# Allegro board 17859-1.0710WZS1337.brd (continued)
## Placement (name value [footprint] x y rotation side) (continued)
PC4702  SC10U25V3MX-GP  [C603H40]  54.22 58.35 90 top
PC4703  SC10U25V3MX-GP  [C603H40]  54.22 56.52 90 top
PC4704  SC10U25V3MX-GP  [C603H40]  54.22 56.52 270 bottom
PC4706  SC1KP50V2KX-1DLGP  [C402H22]  64.56 62.69 90 top
PC4707  SCD22U25V3KX-DL-GP  [C603H36]  48.39 60.96 90 top
PC4708  SC1U10V2KX-1DLGP  [C402H22]  51.33 63.85 270 bottom
PC4766  SC1U10V2KX-1DLGP  [C402H22]  53.79 64.34 180 bottom
PC4802  SC10U25V3MX-GP  [C603H40]  52.55 68.68 90 top
PC4803  SC10U25V3MX-GP  [C603H40]  52.55 68.68 270 bottom
PC4804  SC10U25V3MX-GP  [C603H40]  52.55 66.86 270 bottom
PC4805  SC10U25V3MX-GP  [C603H40]  52.55 66.86 90 top
PC4808  SCD22U25V3KX-DL-GP  [C603H36]  47.77 71.81 90 top
PC4809  SC1U10V2KX-1DLGP  [C402H22]  50.84 74.15 270 bottom
PC4810  SC1KP50V2KX-1DLGP  [C402H22]  55.99 77.54 90 bottom
PC4811  SCD22U25V3KX-DL-GP  [C603H36]  49.5 81.99 90 top
PC4812  SC1U10V2KX-1DLGP  [C402H22]  51.84 88.22 90 top
PC4813  SC1KP50V2KX-1DLGP  [C402H22]  63.88 86.13 270 bottom
PC4814  SC10U25V3MX-GP  [C603H40]  53.84 76.51 270 bottom
PC4815  SC10U25V3MX-GP  [C603H40]  53.84 78.31 270 bottom
PC4816  SC10U25V3MX-GP  [C603H40]  53.84 76.51 90 top
PC4817  SC10U25V3MX-GP  [C603H40]  53.84 78.31 90 top
PC4866  SC1U10V2KX-1DLGP  [C402H22]  53.13 87.76 180 top
PC4877  SC1U10V2KX-1DLGP  [C402H22]  52.78 74.73 180 bottom
PC5001  SC2D2U10V3KX-1DLGP-U  [C603H36]  90.16 105.95 270 top
PC5002  SC10U25V5KX-DL-GP  [C805H58]  89.66 99.94 0 bottom
PC5003  SC10U25V5KX-DL-GP  [C805H58]  90.49 96.89 180 bottom
PC5004  SCD1U25V2KX-1-DL-GP  [C402H22]  90.95 100.42 0 bottom
PC5005  SCD22U25V3KX-DL-GP  [C603H36]  87.9 102.57 90 top
PC5104  SC22U6D3V3MX-L1-GP  [C603H40]  41.83 11.67 0 top
PC5105  SC22U6D3V3MX-L1-GP  [C603H40]  40.56 11.67 0 top
PC5107  SC22U6D3V3MX-L1-GP  [C603H40]  41.7 16.5 180 top
PC5108  SC1U10V2KX-L1-GP  [C402H22]  55.57 10.34 0 bottom
PC5109  SC22U6D3V3MX-L1-GP  [C603H40]  40.43 16.5 180 top
PC5111  SC10U25V3MX-GP  [C603H40]  47.82 16.56 180 top
PC5112  SC4D7U6D3V3KX-L-GP  [C603H36]  57.17 10.85 90 bottom
PC5113  SCD1U25V2KX-L-GP  [C402H22]  56.79 14.53 270 bottom
PC5114  SCD1U25V2KX-L-GP  [C402H22]  49.93 17.43 0 bottom
PC5115  SC10U25V3MX-GP  [C603H40]  48.69 16.77 0 bottom
PC5116  SCD1U25V2KX-L-GP  [C402H22]  50.64 16.13 180 top
PC5117  SC10U6D3V3MX-L-GP  [C603H38]  55.59 16.44 0 bottom
PC5118  SC1500P50V2KX-2GP  [C402H22]  44.34 11.08 270 top
PC5122  SC1U10V2KX-L1-GP  [C402H22]  51.78 16.41 270 top
PC5124  SC10U6D3V3MX-L-GP  [C603H38]  54.1 16.64 0 bottom
PC5125  SC10U6D3V3MX-DL-GP  [C603H36]  74.19 15.37 0 bottom
PC5126  SC68P50V2JN-1DLGP  [C402H22]  63.85 14.3 180 bottom
PC5127  SC22U6D3V5MX-2DLGP  [C805H54]  61.36 12.93 180 bottom
PC5128  SC10U6D3V3MX-DL-GP  [C603H36]  62.2 16.28 0 bottom
PC5129  SCD1U25V2KX-1-DL-GP  [C402H22]  71.67 12.75 0 bottom
PC5130  SC1U10V2KX-1DLGP  [C402H22]  71.95 15.78 0 bottom
PC5201  SC22U6D3V3MX-1-DL-GP  [C603H40]  148.25 56.54 270 top
PC5202  SC1U10V2KX-1GP  [C402H22]  146.37 69.94 90 bottom
PC5203  SC22U6D3V3MX-1-DL-GP  [C603H40]  148.28 57.84 270 top
PC5204  SCD1U25V2KX-GP  [C402H22]  146.65 67.72 180 bottom
PC5205  SC22U6D3V3MX-1-DL-GP  [C603H40]  154.02 56.92 270 bottom
PC5206  SC22U6D3V3MX-1-DL-GP  [C603H40]  148.25 56.54 90 bottom
PC5208  SCD1U25V2KX-GP  [C402H22]  148.38 60.15 270 top
PC5209  SC10U25V5KX-DL-GP  [C805H58]  154.76 65.36 180 bottom
PC5210  SC10U25V5KX-DL-GP  [C805H58]  155.95 69.8 270 bottom
PC5211  SC10U25V5KX-GP  [C805H56]  156.38 68 270 bottom
PC5212  SC220P50V2KX-3GP  [C402H22]  153.44 73.69 90 bottom
PC5213  SCD01U25V2KX-3DLGP  [C402H22]  146.86 70.82 90 bottom
PC5214  SCD1U25V2KX-1-DL-GP  [C402H22]  157.37 67.69 90 top
PC5215  SC1KP50V2KX-1DLGP  [C402H22]  149.88 73.64 0 bottom
PC5216  SC10U25V5KX-GP  [C805H56]  156.56 65.61 180 bottom
PC5301  SC68P50V2JN-1DLGP  [C402H22]  85.52 14.28 180 bottom
PC5302  SC22U6D3V5MX-2DLGP  [C805H54]  82.75 14.38 90 bottom
PC5303  SC10U6D3V3MX-DL-GP  [C603H36]  82.87 15.93 90 bottom
PC5304  SC4700P50V2KX-1DLGP  [C402H22]  91.82 12.45 270 top
PC5305  SC1U10V2KX-1DLGP  [C402H22]  91.98 14.64 0 top
PC5306  SC10U6D3V3MX-DL-GP  [C603H36]  92.45 17.55 270 bottom
PC8501  SCD1U25V2KX-1-DL-GP  [C402H22]  125.37 95.07 0 bottom
PC8502  SC10U25V3MX-GP  [C603H40]  127.15 105.41 180 bottom
PC8503  SC10U25V3MX-GP  [C603H40]  126.44 95 180 top
PC8504  SC10U25V3MX-GP  [C603H40]  127.71 95 180 top
PC8505  SC10U25V3MX-GP  [C603H40]  127.71 95 0 bottom
PC8506  SC1U10V2KX-1DLGP  [C402H22]  123.87 100.08 90 top
PC8507  SCD1U25V2KX-1-DL-GP  [C402H22]  115.23 102.24 270 top
PC8508  SC330P50V2JN-1-DL-GP  [C402H22]  136.65 106.5 270 top
PC8509  SCD1U25V2KX-1-DL-GP  [C402H22]  122.4 104.12 0 top
PC8510  SC1KP50V2KX-1DLGP  [C402H22]  115.77 103.58 180 bottom
PC8511  SC10U25V3MX-GP  [C603H40]  127.15 105.41 0 top
PC8512  SC10U25V3MX-GP  [C603H40]  125.85 105.41 180 bottom
PC8513  SC10U25V3MX-GP  [C603H40]  126.44 95 0 bottom
PC8514  SCD1U16V2KX-3DLGP  [C402H22]  115.49 98.38 270 top
PC8515  SC10U25V3MX-GP  [C603H40]  125.85 105.41 0 top
PC8516  SCD1U25V2KX-1-DL-GP  [C402H22]  124.81 105.21 0 top
PC8517  SCD1U25V2KX-1-DL-GP  [C402H22]  122.52 96.98 180 top
PC8518  SC33P50V2JN-3DLGP  [C402H22]  117.55 100.84 90 bottom
PC8519  SC2700P50V2KX-1-DL-GP  [C402H22]  115.46 97.61 90 top
PC8520  SC330P50V2JN-1-DL-GP  [C402H22]  137.13 94.9 0 top
PC8521  SCD01U25V2KX-3DLGP  [C402H22]  115.64 96.85 90 top
PC8522  SCD1U25V2KX-1-DL-GP  [C402H22]  117.42 104.07 90 top
PC8523  SC47P50V2JN-5DLGP  [C402H22]  118.33 96.04 0 top
PC8524  SC47P50V2JN-5DLGP  [C402H22]  117.49 98.86 180 top
PC8525  SC47P50V2JN-5DLGP  [C402H22]  117.52 95.91 0 top
PC8526  SCD1U25V2KX-1-DL-GP  [C402H22]  119.04 104.04 270 top
PC8602  SC330P50V2KX-3GP  [C402H22]  183.86 57.08 0 top
PC8609  SCD01U25V2KX-3DLGP  [C402H22]  183.56 49.86 0 top
PC8610  SC10U25V3MX-GP  [C603H40]  181.81 49.84 0 top
PC8611  SC22U6D3V3MX-1-DL-GP  [C603H40]  187.73 57.53 180 top
PC8613  SC22U6D3V3MX-1-DL-GP  [C603H40]  190.39 50.9 0 top
PC8614  SCD1U16V2KX-3GP  [C402H22]  188.59 50.88 0 top
PC8615  SC10U25V3MX-GP  [C603H40]  181.65 49.84 180 bottom
PC8616  SCD1U16V2KX-3GP  [C402H22]  180.82 57.2 180 top
PC8617  SC2D2U10V3KX-1GP  [C603H36]  186.43 57.2 180 top
PC8618  SC1U10V2KX-1GP  [C402H22]  185.41 57.31 180 top
PC8619  SCD1U25V2KX-GP  [C402H22]  184.27 50.12 0 bottom
PC8620  SC22U6D3V3MX-1-DL-GP  [C603H40]  189.02 57.53 180 top
PC8621  SC22U6D3V3MX-1-DL-GP  [C603H40]  187.34 50.88 0 top
PC8627  SC10U6D3V3MX-GP  [C603H38]  144.65 87.12 0 bottom
PC8628  SC22U6D3V3MX-1-DL-GP  [C603H40]  152.24 84.53 180 bottom
PC8629  SC1U10V2KX-1GP  [C402H22]  143.38 82.98 90 bottom
PC8630  SC10U6D3V3MX-GP  [C603H38]  143.38 86.85 0 bottom
PC8631  SC22U6D3V3MX-1-DL-GP  [C603H40]  153.51 84.53 180 bottom
PC8632  SC22P50V2JN-4GP  [C402H22]  148.46 82.83 0 bottom
PD4401  BAT54C-12-GP  [SOT-23-9H44]  102.28 16.26 270 bottom
PD4404  L1SS355T1G-GP  [SOD323AKH44]  173.68 17.27 270 bottom
PD4407  RB520S30-GP  [SOD523AKH26]  167.43 4.22 270 top
PD4408  BAT54C-12-GP  [SOT-23-9H44]  106.22 16.23 270 bottom
PD4409  RB751V-40H-GP  [SOD323AKH38]  138.4 16.08 90 top
PD4411  RB520S30-GP  [SOD523AKH26]  139.06 18.62 270 top
PD5101  AZ4024-01L-R7G-GP  [SOD323AKH40]  49.32 17.02 0 top
PDA1  GNDPADSR375-GP  [GNDPADSR351-131-S-NP]  175.51 104.98 0 top
PDA2  GNDPADSR375-GP  [GNDPADSR351-131-S-NP]  175.51 104.98 180 bottom
PG4401  GAP-CLOSE-PWR-3-GP  [GAP-CLOSE-PWR-3]  152.09 12.88 0 bottom
PG4402  GAP-CLOSE-PWR-3-GP  [GAP-CLOSE-PWR-3]  152.09 11.84 0 bottom
PG4405  GAP-CLOSE-PWR-3-GP  [GAP-CLOSE-PWR-3]  133.7 7.7 0 top
PG4406  GAP-CLOSE-PWR-3-GP  [GAP-CLOSE-PWR-3]  133.62 5.87 0 top
PG4408  GAP-CLOSE-PWR-3-GP  [GAP-CLOSE-PWR-3]  159.15 7.32 0 bottom
PG4501  GAP-CLOSE-PWR-3-GP  [GAP-CLOSE-PWR-3]  57.86 7.44 180 bottom
PG4502  GAP-CLOSE-PWR-3-GP  [GAP-CLOSE-PWR-3]  57.85 7.42 180 top
PG4503  GAP-CLOSE-PWR-3-GP  [GAP-CLOSE-PWR-3]  57.85 8.18 180 top
PG4504  GAP-CLOSE-PWR-3-GP  [GAP-CLOSE-PWR-3]  57.86 8.21 180 bottom
PG4505  GAP-CLOSE-PWR-3-GP  [GAP-CLOSE-PWR-3]  57.85 8.95 180 top
PG4506  GAP-CLOSE-PWR-3-GP  [GAP-CLOSE-PWR-3]  57.86 8.97 180 bottom
PG4507  GAP-CLOSE-PWR-3-GP  [GAP-CLOSE-PWR-3]  38.82 7.6 180 bottom
PG4508  GAP-CLOSE-PWR-3-GP  [GAP-CLOSE-PWR-3]  38.82 8.36 180 bottom
PG4509  GAP-CLOSE-PWR-3-GP  [GAP-CLOSE-PWR-3]  38.82 5.31 180 bottom
PG4510  GAP-CLOSE-PWR-3-GP  [GAP-CLOSE-PWR-3]  38.82 6.07 180 bottom
PG4511  GAP-CLOSE-PWR-3-GP  [GAP-CLOSE-PWR-3]  38.82 4.55 180 bottom
PG4512  GAP-CLOSE-PWR-3-GP  [GAP-CLOSE-PWR-3]  38.82 6.84 180 bottom
PG4513  GAP-CLOSE-PWR-3-GP  [GAP-CLOSE-PWR-3]  38.82 3.03 180 bottom
PG4514  GAP-CLOSE-PWR-3-GP  [GAP-CLOSE-PWR-3]  38.82 3.79 180 bottom
PG4515  GAP-CLOSE-PWR-3-GP  [GAP-CLOSE-PWR-3]  198.02 42.58 90 top
PG4516  GAP-CLOSE-PWR-3-GP  [GAP-CLOSE-PWR-3]  199.55 42.58 90 top
PG4517  GAP-CLOSE-PWR-3-GP  [GAP-CLOSE-PWR-3]  198.79 42.58 90 top
PG4518  GAP-CLOSE-PWR-3-GP  [GAP-CLOSE-PWR-3]  197.26 42.58 90 top
PG4519  GAP-CLOSE-PWR-3-GP  [GAP-CLOSE-PWR-3]  183.87 47.07 180 top
PG4520  GAP-CLOSE-PWR-3-GP  [GAP-CLOSE-PWR-3]  183.87 47.83 180 top
PG4521  GAP-CLOSE-PWR-3-GP  [GAP-CLOSE-PWR-3]  183.87 45.54 180 top
PG4522  GAP-CLOSE-PWR-3-GP  [GAP-CLOSE-PWR-3]  183.87 44.02 180 top
PG4523  GAP-CLOSE-PWR-3-GP  [GAP-CLOSE-PWR-3]  183.87 46.31 180 top
PG4524  GAP-CLOSE-PWR-3-GP  [GAP-CLOSE-PWR-3]  183.87 44.78 180 top
PG4527  GAP-CLOSE-PWR-3-GP  [GAP-CLOSE-PWR-3]  39.29 3.38 0 top
PG4528  GAP-CLOSE-PWR-3-GP  [GAP-CLOSE-PWR-3]  53.13 4.27 0 top
PG4529  GAP-CLOSE-PWR-3-GP  [GAP-CLOSE-PWR-3]  58.19 2.9 180 top
PG4530  GAP-CLOSE-PWR-3-GP  [GAP-CLOSE-PWR-3]  185.21 48.14 270 top
PG4531  GAP-CLOSE-PWR-3-GP  [GAP-CLOSE-PWR-3]  200.2 49.1 180 top
PG4532  GAP-CLOSE-PWR-3-GP  [GAP-CLOSE-PWR-3]  194.02 51.21 90 top
PG4533  GAP-CLOSE-PWR-3-GP  [GAP-CLOSE-PWR-3]  56.64 9.91 270 top
PG4534  GAP-CLOSE-PWR-3-GP  [GAP-CLOSE-PWR-3]  55.87 9.91 270 top
PG4707  GAP-CLOSE-PWR-3-GP  [GAP-CLOSE-PWR-3]  60.37 62.82 180 bottom
PG4708  GAP-CLOSE-PWR-3-GP  [GAP-CLOSE-PWR-3]  62.53 62.82 0 bottom
PG4709  GAP-CLOSE-PWR-3-GP  [GAP-CLOSE-PWR-3]  43.58 108.59 90 top
PG4710  GAP-CLOSE-PWR-3-GP  [GAP-CLOSE-PWR-3]  42.82 108.59 90 top
PG4711  GAP-CLOSE-PWR-3-GP  [GAP-CLOSE-PWR-3]  42.06 108.59 90 top
PG4712  GAP-CLOSE-PWR-3-GP  [GAP-CLOSE-PWR-3]  41.29 108.59 90 top
PG4713  GAP-CLOSE-PWR-3-GP  [GAP-CLOSE-PWR-3]  40.53 108.59 90 top
PG4714  GAP-CLOSE-PWR-3-GP  [GAP-CLOSE-PWR-3]  50.39 62.99 0 bottom
PG4715  GAP-CLOSE-PWR-3-GP  [GAP-CLOSE-PWR-3]  50.39 62.23 0 bottom
PG4716  GAP-CLOSE-PWR-3-GP  [GAP-CLOSE-PWR-3]  50.39 61.47 0 bottom
PG4717  GAP-CLOSE-PWR-3-GP  [GAP-CLOSE-PWR-3]  50.39 60.71 0 bottom
PG4718  GAP-CLOSE-PWR-3-GP  [GAP-CLOSE-PWR-3]  50.39 59.95 0 bottom
PG4808  GAP-CLOSE-PWR-3-GP  [GAP-CLOSE-PWR-3]  60.41 72.64 180 bottom
PG4809  GAP-CLOSE-PWR-3-GP  [GAP-CLOSE-PWR-3]  62.7 72.64 0 bottom
PG4813  GAP-CLOSE-PWR-3-GP  [GAP-CLOSE-PWR-3]  60.35 81.83 180 bottom
PG4815  GAP-CLOSE-PWR-3-GP  [GAP-CLOSE-PWR-3]  62.63 81.85 0 bottom
PG4816  GAP-CLOSE-PWR-3-GP  [GAP-CLOSE-PWR-3]  49.55 76.74 0 top
PG4817  GAP-CLOSE-PWR-3-GP  [GAP-CLOSE-PWR-3]  49.55 77.5 0 top
PG4818  GAP-CLOSE-PWR-3-GP  [GAP-CLOSE-PWR-3]  49.55 78.26 0 top
PG4819  GAP-CLOSE-PWR-3-GP  [GAP-CLOSE-PWR-3]  49.55 79.02 0 top
PG4820  GAP-CLOSE-PWR-3-GP  [GAP-CLOSE-PWR-3]  49.55 79.78 0 top
PG4821  GAP-CLOSE-PWR-3-GP  [GAP-CLOSE-PWR-3]  49.47 78.97 0 bottom
PG4822  GAP-CLOSE-PWR-3-GP  [GAP-CLOSE-PWR-3]  49.47 78.21 0 bottom
PG4823  GAP-CLOSE-PWR-3-GP  [GAP-CLOSE-PWR-3]  49.47 77.45 0 bottom
PG4824  GAP-CLOSE-PWR-3-GP  [GAP-CLOSE-PWR-3]  49.04 76.23 270 bottom
PG4825  GAP-CLOSE-PWR-3-GP  [GAP-CLOSE-PWR-3]  48.28 76.23 270 bottom
PG5001  GAP-CLOSE-PWR-3-GP  [GAP-CLOSE-PWR-3]  100.76 100.43 0 bottom
PG5002  GAP-CLOSE-PWR-3-GP  [GAP-CLOSE-PWR-3]  86.92 97.85 180 bottom
PG5003  GAP-CLOSE-PWR-3-GP  [GAP-CLOSE-PWR-3]  86.92 98.61 180 bottom
PG5011  GAP-CLOSE-PWR-3-GP  [GAP-CLOSE-PWR-3]  98.55 100.43 180 bottom
PG5101  GAP-CLOSE-PWR-3-GP  [GAP-CLOSE-PWR-3]  50.59 13.13 180 top
PG5102  GAP-CLOSE-PWR-3-GP  [GAP-CLOSE-PWR-3]  50.59 13.9 180 top
PG5103  GAP-CLOSE-PWR-3-GP  [GAP-CLOSE-PWR-3]  50.59 14.84 180 top
PG5106  GAP-CLOSE-PWR-3-GP  [GAP-CLOSE-PWR-3]  38.65 15.48 180 bottom
PG5107  GAP-CLOSE-PWR-3-GP  [GAP-CLOSE-PWR-3]  38.65 12.43 180 bottom
PG5108  GAP-CLOSE-PWR-3-GP  [GAP-CLOSE-PWR-3]  38.65 13.2 180 bottom
PG5109  GAP-CLOSE-PWR-3-GP  [GAP-CLOSE-PWR-3]  38.65 13.96 180 bottom
PG5110  GAP-CLOSE-PWR-3-GP  [GAP-CLOSE-PWR-3]  52.09 17.5 270 top
PG5111  GAP-CLOSE-PWR-3-GP  [GAP-CLOSE-PWR-3]  38.65 16.24 180 bottom
PG5113  GAP-CLOSE-PWR-3-GP  [GAP-CLOSE-PWR-3]  39.41 11.76 90 top
PG5115  GAP-CLOSE-PWR-3-GP  [GAP-CLOSE-PWR-3]  38.65 14.72 180 bottom
PG5116  GAP-CLOSE-PWR-3-GP  [GAP-CLOSE-PWR-3]  53.03 17.5 270 top
PG5120  GAP-CLOSE-PWR-3-GP  [GAP-CLOSE-PWR-3]  57.17 16.67 180 bottom
PG5121  GAP-CLOSE-PWR-3-GP  [GAP-CLOSE-PWR-3]  57.17 15.75 180 bottom
PG5122  GAP-CLOSE-PWR-3-GP  [GAP-CLOSE-PWR-3]  60.27 15.52 90 bottom
PG5123  GAP-CLOSE-PWR-3-GP  [GAP-CLOSE-PWR-3]  61.03 15.52 90 bottom
PG5201  GAP-CLOSE-PWR-3-GP  [GAP-CLOSE-PWR-3]  152.23 55.58 270 bottom
PG5204  GAP-CLOSE-PWR-3-GP  [GAP-CLOSE-PWR-3]  152.99 55.81 270 top
PG5206  GAP-CLOSE-PWR-3-GP  [GAP-CLOSE-PWR-3]  150.71 55.58 270 bottom
PG5207  GAP-CLOSE-PWR-3-GP  [GAP-CLOSE-PWR-3]  152.99 55.58 270 bottom
PG5208  GAP-CLOSE-PWR-3-GP  [GAP-CLOSE-PWR-3]  152.23 55.81 270 top
PG5209  GAP-CLOSE-PWR-3-GP  [GAP-CLOSE-PWR-3]  150.71 55.81 270 top
PG5210  GAP-CLOSE-PWR-3-GP  [GAP-CLOSE-PWR-3]  157.82 69.71 180 top
PG5211  GAP-CLOSE-PWR-3-GP  [GAP-CLOSE-PWR-3]  151.47 55.81 270 top
PG5212  GAP-CLOSE-PWR-3-GP  [GAP-CLOSE-PWR-3]  157.82 68.95 180 top
PG5213  GAP-CLOSE-PWR-3-GP  [GAP-CLOSE-PWR-3]  149.95 55.81 270 top
PG5214  GAP-CLOSE-PWR-3-GP  [GAP-CLOSE-PWR-3]  157.82 70.47 180 top
PG5215  GAP-CLOSE-PWR-3-GP  [GAP-CLOSE-PWR-3]  149.95 55.58 270 bottom
PG5216  GAP-CLOSE-PWR-3-GP  [GAP-CLOSE-PWR-3]  151.47 55.58 270 bottom
PG5223  GAP-CLOSE-PWR-6-GP  [GAP-CLOSE-PWR]  154.22 55.83 180 bottom
PG5301  GAP-CLOSE-PWR-3-GP  [GAP-CLOSE-PWR-3]  83.28 15.88 90 top
PG5302  GAP-CLOSE-PWR-3-GP  [GAP-CLOSE-PWR-3]  81.76 15.88 90 top
PG5303  GAP-CLOSE-PWR-3-GP  [GAP-CLOSE-PWR-3]  82.52 15.88 90 top
PG8605  GAP-CLOSE-PWR-3-GP  [GAP-CLOSE-PWR-3]  144.8 81.74 90 bottom
PG8606  GAP-CLOSE-PWR-3-GP  [GAP-CLOSE-PWR-3]  144.04 81.74 90 bottom
PG8607  GAP-CLOSE-PWR-3-GP  [GAP-CLOSE-PWR-3]  154.91 85.58 0 bottom
PG8608  GAP-CLOSE-PWR-3-GP  [GAP-CLOSE-PWR-3]  154.91 84.81 0 bottom
PG8609  GAP-CLOSE-PWR-3-GP  [GAP-CLOSE-PWR-3]  190.7 52.17 0 bottom
PG8610  GAP-CLOSE-PWR-3-GP  [GAP-CLOSE-PWR-3]  190.7 53.7 0 bottom
PG8611  GAP-CLOSE-PWR-3-GP  [GAP-CLOSE-PWR-3]  190.7 52.94 0 bottom
PG8612  GAP-CLOSE-PWR-3-GP  [GAP-CLOSE-PWR-3]  190.7 51.41 0 bottom
PG8613  GAP-CLOSE-PWR-3-GP  [GAP-CLOSE-PWR-3]  190.11 57.1 90 top
PG8614  GAP-CLOSE-PWR-3-GP  [GAP-CLOSE-PWR-3]  178.18 53.11 0 top
PG8615  GAP-CLOSE-PWR-3-GP  [GAP-CLOSE-PWR-3]  178.18 52.35 0 top
PG8616  GAP-CLOSE-PWR-3-GP  [GAP-CLOSE-PWR-3]  178.18 51.59 0 top
PG8617  GAP-CLOSE-PWR-3-GP  [GAP-CLOSE-PWR-3]  178.18 50.83 0 top
PG8618  GAP-CLOSE-PWR-3-GP  [GAP-CLOSE-PWR-3]  190.7 56.75 0 bottom
PG8619  GAP-CLOSE-PWR-3-GP  [GAP-CLOSE-PWR-3]  190.7 54.46 0 bottom
PG8620  GAP-CLOSE-PWR-3-GP  [GAP-CLOSE-PWR-3]  190.7 55.22 0 bottom
PG8621  GAP-CLOSE-PWR-3-GP  [GAP-CLOSE-PWR-3]  190.7 55.98 0 bottom
PL4401  IND-4D7UH-291-GP  [L11102530H158]  142.92 11.36 90 bottom
PL4501  COIL-1D5UH-43-GP  [L4947-1015H119]  189.43 46.41 90 bottom
PL4502  IND-1D5UH-23-GP-U  [L7066-1830-UH119]  44.75 5.54 270 bottom
PL4701  COIL-D15UH-2-GP  [L7366-1930H158]  61.47 62.82 270 bottom
PL4801  COIL-D15UH-2-GP  [L7366-1930H158]  61.55 72.64 270 bottom
PL4802  COIL-D15UH-2-GP  [L7366-1930H158]  61.5 81.95 270 bottom
PL5001  IND-D47UH-22-GP-U  [L7066-1830-UH119]  99.67 100.7 270 bottom
PL5101  COIL-1UH-34-GP-U1  [L7066-1830-UH119]  43.63 13.59 90 bottom
PL5201  COIL-1UH-34-GP-U1  [L7066-1830-UH119]  150.13 61.67 180 bottom
PL8508  IND-D15UH-33-GP  [L7366-1830H119]  139.54 103.91 270 bottom
PL8509  IND-D15UH-33-GP  [L7366-1830H119]  139.54 96.8 270 bottom
PL8602  IND-1UH-300-GP  [L2520-D620H48]  149.96 86.52 270 bottom
PL8603  COIL-1UH-73-GP  [L4947-1115H119]  186.91 53.55 270 bottom
PQ4402  2N7002K-2-GP  [SOT23DGS2D4H44]  214.17 58.37 0 top
PQ4405  2N7002KDW-1-GP  [SOT-363H44]  169.21 12.91 180 bottom
PQ4408  MMBT3906-3-GP  [SOT23CBE2D4H44]  166.54 15.95 270 bottom
PQ4415  2N7002KDW-1-GP  [SOT-363H44]  165.09 7.34 270 bottom
PQ4416  2N7002KDW-1-GP  [SOT-363H44]  166.31 10.62 180 bottom
PQ4417  2N7002K-2-GP  [SOT23DGS2D4H44]  96.95 5.87 0 top
PQ4418  2N7002KDW-1-GP  [SOT-363H44]  99.89 9.43 0 top
PR4401  D01R6F-1-GP  [R1206H38]  150.16 12.45 180 bottom
PR4402  2D2R3-1-U-GP  [R603H22]  165.88 13.46 270 top
PR4403  2D2R5J-1-GP  [R805H24]  164.33 4.93 90 top
PR4404  150KR2F-L-GP  [R402H16]  156.97 4.63 180 top
PR4405  4D7R2F-GP  [R402H16]  161.87 5.44 270 top
PR4406  18K7R2F-GP  [R402H16]  158.52 4.68 0 top
PR4407  D01R3721F-GP-U  [R3720H40]  131.46 6.71 0 top
PR4409  100KR2F-L1-GP  [R402H16]  157.02 6.91 180 bottom
PR4410  105KR2F-1-GP  [R402H16]  155.77 7.57 270 bottom
PR4411  100R2F-L1-GP-U  [R402H14]  155.87 9.2 90 bottom
PR4412  -  [0R0402-PAD]  155.75 10.75 270 bottom
PR4413  12K1R2F-L1-GP  [R402H16]  155.75 11.51 90 bottom
PR4414  -  [0R0805-PAD]  165.91 13.03 270 bottom
PR4416  2D2R3J-2-GP  [R603H22]  142.41 5.46 270 top
PR4417  100KR2F-L1-GP  [R402H16]  161.59 6.91 0 bottom
PR4420  0R3J-0-U-GP  [R603H22]  160.95 15.83 180 top
PR4422  1R2F-GP  [R402H16]  168.14 8.23 270 top
PR4423  2D2R2F-GP  [R402H16]  168.55 8.99 270 top
PR4424  2D2R2F-GP  [R402H16]  157.75 17.83 0 top
PR4425  0R2F-1-GP  [R402H16]  156.97 17.83 0 top
PR4426  196KR2F-GP  [R402H16]  172.23 6.28 90 top
PR4427  100KR2F-L2-GP  [R402H16]  169.49 4.98 0 top
PR4429  100KR2F-L2-GP  [R402H16]  159.1 6.45 90 bottom
PR4430  100KR2J-1-GP  [R402H16]  97.35 7.83 270 top
PR4431  -  [0R0402-PAD]  99.05 6.76 0 top
PR4432  0R2J-L-GP  [R402H15]  99.82 6.12 0 top
PR4433  -  [0R0402-PAD]  99.71 4.9 270 top
PR4434  0R2F-1-GP  [R402H16]  167.38 6.28 90 top
PR4435  100KR2F-L3-GP  [R402H16]  168.98 9.83 90 bottom
PR4436  1MR2J-1-GP  [R402H16]  167.25 16.82 180 top
PR4437  0R2F-1-GP  [R402H16]  168.14 5.51 90 top
PR4438  0R2J-2-GP  [R402H16]  160.98 16.16 180 bottom
PR4439  1KR2F-3-GP  [R402H16]  153.11 8.26 270 bottom
PR4440  D001R2512F-8-GP  [R2512-4H35]  133.19 9.22 90 bottom
PR4441  0R3J-0-U-GP  [R603H22]  141.45 12.37 90 top
PR4443  0R3J-0-U-GP  [R603H22]  154.71 16.46 270 bottom
PR4444  0R0603-PAD-1-GP-U  [0R0603-PAD-U]  162.58 15.65 90 bottom
PR4445  0R2F-1-GP  [R402H16]  162.78 14 270 top
PR4446  0R3J-0-U-GP  [R603H22]  162.22 15.57 0 top
PR4447  127KR2F-GP  [R402H16]  154.71 7.22 270 top
PR4448  200KR2F-L-GP  [R402H16]  154.71 6.45 90 top
PR4449  200KR2F-L-GP  [R402H16]  170.25 4.98 0 top
PR4450  10KR2F-2-GP  [R402H16]  170.53 13.54 90 top
PR4451  95K3R2F-GP  [R402H16]  160.83 6.91 180 bottom
PR4453  0R2J-2-GP  [R402H16]  159.94 16.44 0 top
PR4462  -  [0R0402-PAD]  164.64 16.72 0 top
PR4463  0R2J-2-GP  [R402H16]  171.34 8.36 0 top
PR4464  10KR2F-2-GP  [R402H16]  97.45 9.63 0 top
PR4465  100KR2F-L1-GP  [R402H16]  99.08 11.74 0 top
PR4466  0R2J-2-GP  [R402H16]  118.41 14.18 90 top
PR4472  100KR2F-L3-GP  [R402H16]  170.25 10.29 0 bottom
PR4473  100KR2J-1-GP  [R402H16]  168.52 16.84 0 top
PR4474  100KR2F-L1-GP  [R402H16]  168.22 15.32 90 top
PR4475  680KR2F-GP  [R402H16]  165.4 16.72 180 top
PR4476  -  [0R0402-PAD]  169.51 9.96 90 top
PR4477  0R0402-PAD-1-GP  [0R0402-PAD]  171.75 14.35 0 top
PR4478  100R2F-L1-GP-U  [R402H14]  154.91 13.95 90 bottom
PR4479  D001R2512F-8-GP  [R2512-4H35]  151.38 11.36 180 top
PR4480  0R2F-1-GP  [R402H16]  159 15.57 0 bottom
PR4483  D01R3721F-GP-U  [R3720H40]  122.3 4.93 180 top
PR4484  0R2F-1-GP  [R402H16]  159.79 5.44 90 top
PR4485  182KR2F-GP  [R402H16]  159.79 6.23 270 top
PR4486  0R0402-PAD-1-GP  [0R0402-PAD]  157.93 15.83 180 top
PR4487  0R0402-PAD-1-GP  [0R0402-PAD]  156.18 16.51 90 top
PR4488  0R0402-PAD-1-GP  [0R0402-PAD]  165.93 7.75 270 top
PR4489  0R0402-PAD-1-GP  [0R0402-PAD]  167.61 11.1 270 top
PR4490  0R2F-1-GP  [R402H16]  165.53 11.99 0 top
PR4491  7K15R2F-L-GP  [R402H16]  166.29 11.99 180 top
PR4492  NTC-220K-5-GP-U  [NTC-402H24-U]  168.65 13.29 180 top
PR4493  0R2F-1-GP  [R402H16]  156.13 8.84 180 top
PR4494  470KR2J-L1-GP  [R402H15]  135.58 17.3 270 top
PR4495  0R2J-2-GP  [R402H16]  138.78 17.35 270 top
PR4496  D01R3721F-GP-U  [R3720H40]  126.69 11.61 0 top
PR4501  -  [0R0603-PAD]  191.92 43.46 0 top
PR4502  -  [0R0603-PAD]  49.91 6.71 270 top
PR4503  10KR2F-2-GP  [R402H16]  194.53 52.38 90 top
PR4504  0R0402-PAD-1-GP  [0R0402-PAD]  54.27 2.49 0 bottom
PR4505  100KR2J-1-GP  [R402H16]  200.2 49.99 270 top
PR4506  1KR2F-3-GP  [R402H16]  194.91 51.13 180 top
PR4507  1KR2F-3-GP  [R402H16]  52.75 2.24 0 bottom
PR4508  200KR2F-L1-GP  [R402H16]  199.46 51.69 270 top
PR4509  1KR2F-3-GP  [R402H16]  200.04 50.9 270 top
PR4510  100KR2J-1-GP  [R402H16]  57.07 3.3 180 top
PR4511  1KR2F-3-GP  [R402H16]  57.14 2.18 0 bottom
PR4512  200KR2F-L1-GP  [R402H16]  55.8 2.49 180 bottom
PR4513  1MR2J-1-GP  [R402H16]  55.04 2.49 180 bottom
PR4514  1MR2J-1-GP  [R402H16]  197.12 52.43 90 top
PR4515  0R0402-PAD-1-GP  [0R0402-PAD]  195.78 52.83 0 top
PR4516  0R0402-PAD-1-GP  [0R0402-PAD]  197.12 53.22 270 top
PR4530  10KR2F-2-GP  [R402H16]  194.53 53.27 90 top
PR4551  348KR2F-GP  [R402H16]  53.51 2.24 0 top
PR4601  0R0402-PAD-1-GP  [0R0402-PAD]  48.94 66.68 270 bottom
PR4602  0R0402-PAD-1-GP  [0R0402-PAD]  48.61 65.92 270 bottom
PR4603  1KR2F-3-GP  [R402H16]  38.68 62.03 0 top
PR4604  100R2F-L3-GP  [R402H16]  40.96 62.03 0 top
PR4605  75R2F-2-GP  [R402H16]  40.2 62.03 0 top
PR4606  45D3R2F-L-GP  [R402H16]  39.44 62.03 0 top
PR4607  100R2F-L3-GP  [R402H16]  37.64 61.29 0 bottom
PR4608  76K8R2F-GP  [R402H16]  36.21 62.72 90 top
PR4609  10KR2F-L1-GP  [R402H15]  36.86 61.49 0 bottom
PR4610  1R2J-GP  [R402H16]  41.17 60.15 0 bottom
PR4611  NTC-10K-26-GP-U  [NTC-402H22-U]  97.15 105.9 90 bottom
PR4612  0R0402-PAD-1-GP  [0R0402-PAD]  43.73 60.89 0 bottom
PR4613  0R0402-PAD-1-GP  [0R0402-PAD]  46.53 63.97 270 bottom
PR4614  0R2J-L-GP  [R402H15]  38.42 64.26 180 top
PR4615  1KR2F-3-GP  [R402H16]  46.3 63.07 90 bottom
PR4616  8K06R2F-GP  [R402H16]  35.12 61.85 90 bottom
PR4617  NTC-470K-8-GP-U  [NTC-402H22-U]  49.07 68.86 0 top
PR4618  11KR2F-L-GP  [R402H16]  45.1 65.18 180 bottom
PR4620  430R2F-GP  [R402H16]  44.27 64.39 180 bottom
PR4621  27K4R2F-GP  [R402H16]  33.3 60.43 0 bottom
PR4622  10R2F-L1-GP  [R402H16]  40.23 61.09 0 bottom
PR4623  0R0402-PAD-1-GP  [0R0402-PAD]  39.47 61.34 0 bottom
PR4624  49D9R2F-L1-GP  [R402H16]  38.14 59.59 90 bottom
PR4625  2K61R2F-1-GP  [R402H16]  48.96 65.13 270 bottom
PR4626  3K3R2F-2-GP  [R402H16]  35.12 62.61 270 bottom
PR4627  100R2F-L1-GP-U  [R402H14]  41.12 64.85 90 top
PR4628  9K31R2F-GP  [R402H16]  46.25 62.28 270 bottom
PR4629  100KR2F-L1-GP  [R402H16]  46.02 61.51 270 bottom
PR4630  2KR2F-L1-GP  [R402H16]  35.12 63.38 270 bottom
PR4631  100R2F-L1-GP-U  [R402H14]  31.34 64.49 90 bottom
PR4632  301R2F-GP  [R402H16]  46.25 68.07 90 bottom
PR4633  2K55R2F-GP  [R402H16]  35.12 64.14 270 bottom
PR4635  1KR2F-3-GP  [R402H16]  36.04 73.87 180 bottom
PR4636  499R2F-2-GP  [R402H16]  35.18 65.68 270 bottom
PR4637  1K78R2F-GP  [R402H16]  46.25 67.31 270 bottom
PR4638  2KR2F-L1-GP  [R402H16]  45 67.54 180 bottom
PR4639  100R2F-L1-GP-U  [R402H14]  35.43 66.93 0 bottom
PR4640  2K49R2F-2-L-GP  [R402H16]  45.03 69.27 0 bottom
PR4641  2K61R2F-1-GP  [R402H16]  32.76 68.3 0 bottom
PR4642  357R2F-GP  [R402H16]  34.8 70.06 90 bottom
PR4643  11KR2F-L-GP  [R402H16]  33.53 68.29 0 bottom
PR4644  40K2R2F-GP  [R402H16]  41.08 67 270 top
PR4645  1KR2F-L1-GP  [R402H15]  34.79 70.85 90 bottom
PR4646  NTC-10K-26-GP-U  [NTC-402H22-U]  56.92 67.92 270 bottom
PR4647  0R0402-PAD-1-GP  [0R0402-PAD]  33.09 70.36 90 bottom
PR4648  255R2F-L-GP  [R402H16]  45 70.51 270 bottom
PR4649  0R0402-PAD-1-GP  [0R0402-PAD]  45.18 73.56 180 bottom
PR4650  NTC-10K-26-GP-U  [NTC-402H22-U]  56.92 67.13 90 bottom
PR4651  1KR2F-L1-GP  [R402H15]  45 71.28 270 bottom
PR4652  11KR2F-L-GP  [R402H16]  43.96 73.15 270 bottom
PR4653  2K61R2F-1-GP  [R402H16]  44.04 75.47 270 bottom
PR4654  NTC-470K-8-GP-U  [NTC-402H22-U]  48.43 59.67 270 top
PR4655  27K4R2F-GP  [R402H16]  37.13 73.64 180 bottom
PR4656  2K87R2F-1-GP  [R402H16]  38.81 73.69 0 bottom
PR4657  2KR2F-L1-GP  [R402H16]  40.66 71.78 90 bottom
PR4658  499R2F-2-GP  [R402H16]  40.35 73.08 0 bottom
PR4659  100R2F-L1-GP-U  [R402H14]  42.36 71.78 270 bottom
PR4660  1K91R2F-1-GP  [R402H16]  41.11 73.08 0 bottom
PR4661  84K5R2F-GP  [R402H16]  37.52 74.89 270 bottom
PR4662  10KR2F-L1-GP  [R402H15]  39.01 71.35 45 bottom
PR4663  100R2F-L1-GP-U  [R402H14]  40.58 75.87 270 bottom
PR4665  0R0402-PAD-1-GP  [0R0402-PAD]  31.34 65.26 270 bottom
PR4666  0R0402-PAD-1-GP  [0R0402-PAD]  31.41 67.8 270 bottom
PR4667  0R0402-PAD-1-GP  [0R0402-PAD]  41.88 74.64 180 bottom
PR4668  0R0402-PAD-1-GP  [0R0402-PAD]  42.7 74.63 180 bottom
PR4669  0R2J-L-GP  [R402H15]  36.04 72.04 180 bottom
PR4670  267R2F-1-GP  [R402H16]  35.55 69.14 90 bottom
PR4671  1K54R2F-GP  [R402H16]  35.17 64.92 270 bottom
PR4672  100KR2F-L1-GP  [R402H16]  36.21 61.95 90 top
PR4701  0R0402-PAD-1-GP  [0R0402-PAD]  46.68 71.94 90 bottom
PR4702  0R0402-PAD-1-GP  [0R0402-PAD]  49.17 65.48 270 top
PR4703  2D2R6J-3-GP  [R1206H28]  61.26 62.69 90 top
PR4704  2D2R2F-GP  [R402H16]  51.31 64.62 270 bottom
PR4705  2D2R3F-L-GP  [R603H24]  48.38 62.23 90 top
PR4706  0R0402-PAD-1-GP  [0R0402-PAD]  49.17 64.71 270 top
PR4708  3K65R2F-1-GP  [R402H16]  44.19 76.23 90 bottom
PR4712  5K11R2F-L1-GP  [R402H16]  49.17 66.25 270 top
PR4802  0R0402-PAD-1-GP  [0R0402-PAD]  48.08 75.82 270 top
PR4803  2D2R2F-GP  [R402H16]  51.51 74.91 270 bottom
PR4804  2D2R3-1-U-GP  [R603H22]  47.24 73.08 90 top
PR4805  2D2R6J-3-GP  [R1206H28]  58.78 77.32 90 bottom
PR4806  0R0402-PAD-1-GP  [0R0402-PAD]  47.97 74.21 270 top
PR4808  3K65R2F-1-GP  [R402H16]  32.28 72.7 270 bottom
PR4809  10R2F-L1-GP  [R402H16]  33.22 71.66 270 bottom
PR4810  2D2R3-1-U-GP  [R603H22]  48.69 83.26 90 top
PR4811  0R0402-PAD-1-GP  [0R0402-PAD]  49.45 86.44 270 top
PR4812  0R0402-PAD-1-GP  [0R0402-PAD]  49.83 84.41 270 top
PR4813  2D2R2F-GP  [R402H16]  51.89 87.38 90 top
PR4814  2D2R6J-3-GP  [R1206H28]  61.13 86.57 270 bottom
PR4815  10R2F-L1-GP  [R402H16]  32.28 73.46 90 bottom
PR4816  3K65R2F-1-GP  [R402H16]  33.93 75.77 270 bottom
PR4817  5K11R2F-L1-GP  [R402H16]  48.08 75.02 270 top
PR4818  5K11R2F-L1-GP  [R402H16]  50.67 87.38 0 top
PR4821  100KR2F-L1-GP  [R402H16]  34.67 72.49 90 bottom
PR4822  100KR2F-L1-GP  [R402H16]  33.09 74.98 270 bottom
PR4823  100KR2F-L1-GP  [R402H16]  35.2 74.58 0 bottom
PR4824  100KR2F-L1-GP  [R402H16]  34.67 73.26 270 bottom
PR5001  2D2R3F-L-GP  [R603H24]  87.29 104.4 180 top
PR5003  3K65R2F-1-GP  [R402H16]  99.53 105.26 0 bottom
PR5004  0R0402-PAD-1-GP  [0R0402-PAD]  100.3 105.26 0 bottom
PR5101  10K2R2F-GP  [R402H16]  54.53 13.72 180 top
PR5102  6K49R2F-1-GP  [R402H16]  54.27 9.96 90 bottom
PR5103  510KR2F-GP  [R402H16]  57.35 12.22 90 bottom
PR5104  100KR2J-1-GP  [R402H16]  59.58 11.92 90 bottom
PR5105  0R0402-PAD-1-GP  [0R0402-PAD]  57.35 12.98 90 bottom
PR5106  0R0402-PAD-1-GP  [0R0402-PAD]  57.7 13.74 90 bottom
PR5107  6K2R2F-GP  [R402H16]  56.23 13.77 0 top
PR5108  10R2J-L-GP  [R402H16]  57.86 9.86 90 bottom
PR5109  0R0402-PAD-1-GP  [0R0402-PAD]  59.58 12.7 90 bottom
PR5110  2D2R6J-3-GP  [R1206H28]  47.19 11.08 270 top
PR5111  0R0805-PAD-1-GP-U  [0R0805-PAD-U]  51.25 16.79 0 bottom
PR5112  29K4R2F-GP  [R402H16]  62.68 14.3 180 bottom
PR5113  13K7R2F-GP  [R402H16]  63.85 12.73 180 bottom
PR5114  10KR2F-2-GP  [R402H16]  71.98 13.9 90 bottom
PR5115  47KR2J-2-GP  [R402H16]  72.46 12.68 0 bottom
PR5116  0R0402-PAD-1-GP  [0R0402-PAD]  74.26 12.68 180 bottom
PR5201  88K7R2F-GP  [R402H16]  153.64 70.77 0 bottom
PR5202  3K16R2F-GP  [R402H16]  153.41 72.93 90 bottom
PR5203  100KR2F-L1-GP  [R402H16]  150.64 73.89 0 bottom
PR5204  10KR2F-2-GP  [R402H16]  152.04 72.77 0 bottom
PR5206  0R0402-PAD-1-GP  [0R0402-PAD]  147.9 72.98 270 bottom
PR5207  0R0402-PAD-1-GP  [0R0402-PAD]  149.12 73.56 180 bottom
PR5208  100KR2J-1-GP  [R402H16]  147.9 73.74 270 bottom
PR5301  0R0402-PAD-1-GP  [0R0402-PAD]  94.94 14.86 0 top
PR5302  13K3R2F-L1-GP  [R402H16]  85.47 12.6 180 bottom
PR5303  17K4R2F-GP  [R402H16]  84.73 14.28 180 bottom
PR5304  100KR2F-L1-GP  [R402H16]  94.08 14.86 0 top
PR5305  0R0402-PAD-1-GP  [0R0402-PAD]  94.08 13.16 0 top
PR5306  47KR2J-2-GP  [R402H16]  91.77 13.23 270 top
PR8501  2D2R5F-2-GP  [R805H24]  136.27 105.18 90 top
PR8502  2D2R3J-2-GP  [R603H22]  123.82 98.81 270 top
PR8503  2D2R2F-GP  [R402H16]  115.79 103.63 0 top
PR8504  499KR2F-1-GP  [R402H16]  114.88 99.93 90 top
PR8505  100KR2J-1-GP  [R402H16]  120.24 95.96 180 top
PR8506  -  [0R0603-PAD]  121.13 104.12 180 top
PR8507  0R0402-PAD-1-GP  [0R0402-PAD]  116.53 103.58 180 bottom
PR8508  15K4R2F-GP  [R402H16]  123.9 101.12 90 top
PR8509  -  [0R0603-PAD]  121.25 96.38 0 top
PR8510  20KR2F-L-GP  [R402H16]  114.88 100.69 270 top
PR8511  20KR2F-L-GP  [R402H16]  114.75 102.09 90 bottom
PR8512  2KR2F-3-GP  [R402H16]  114.32 97.72 180 top
PR8513  2D2R5F-2-GP  [R805H24]  136.29 96.62 90 top
PR8514  18KR2F-GP  [R402H16]  113.81 96.34 90 top
PR8515  10KR2J-3-GP  [R402H16]  117.29 105.59 90 top
PR8516  -  [0R0402-PAD]  117.42 106.35 90 top
PR8517  10KR2J-3-GP  [R402H16]  117.29 104.83 270 top
PR8518  100R2F-L1-GP-U  [R402H14]  117.09 97.11 270 bottom
PR8519  -  [0R0402-PAD]  117.52 98.55 270 bottom
PR8520  -  [0R0402-PAD]  115.51 99.16 270 top
PR8521  100R2F-L1-GP-U  [R402H14]  116.76 95.96 0 top
PR8522  1KR2J-1-GP  [R402H16]  118.97 105.59 270 top
PR8523  13KR2F-GP  [R402H16]  118.97 104.83 270 top
PR8525  0R2J-2-GP  [R402H16]  118.38 97.16 270 top
PR8526  0R2J-2-GP  [R402H16]  118.79 99.04 180 bottom
PR8527  0R2J-2-GP  [R402H16]  119.58 99.04 180 bottom
PR8561  0R2J-2-GP  [R402H16]  115.49 96.09 270 top
PR8576  0R2J-2-GP  [R402H16]  117.52 99.32 270 bottom
PR8577  160KR2F-GP  [R402H16]  117.52 100.08 90 bottom
PR8613  34K8R2F-1-GP  [R402H16]  149.24 82.93 0 bottom
PR8620  51KR2F-L-GP  [R402H16]  147.72 84.23 270 bottom
PR8623  0R0402-PAD-1-GP  [0R0402-PAD]  146.5 83.06 180 bottom
PR8625  10KR2J-3-GP  [R402H16]  145.74 83.06 0 bottom
PR8626  12KR2F-L-GP  [R402H16]  182.34 57.23 180 top
PR8627  15KR2F-GP  [R402H16]  183.1 57.23 0 top
PR8631  0R0402-PAD-1-GP  [0R0402-PAD]  180 57.13 0 top
PR8632  0R2J-L-GP  [R402H15]  181.58 57.23 0 top
PR8633  0R0603-PAD-1-GP-U  [0R0603-PAD-U]  183.18 49.96 180 bottom
PR8634  0R0402-PAD-1-GP  [0R0402-PAD]  184.63 57.23 180 top
PR8635  0R0402-PAD-1-GP  [0R0402-PAD]  178.66 58.63 90 top
PR8636  100KR2F-L1-GP  [R402H16]  179.11 57.41 180 top
PT4701  SE330U2VDM-4-GP  [CT7343H83]  68.24 65.2 0 bottom
PT4702  SE33U25VM-11-GP  [CT7343H83]  48.69 56.85 90 bottom
PT4801  SE330U2VDM-4-GP  [CT7343H83]  68.27 73.45 180 bottom
PT4803  SE330U2VDM-4-GP  [CT7343H83]  68.27 81.55 0 bottom
PT4805  SE33U25VM-11-GP  [CT7343H83]  50.03 81.84 90 bottom
PT8501  SE330U2VDM-4-GP  [CT7343H83]  148.13 104.09 270 bottom
PT8502  SE330U2VDM-4-GP  [CT7343H83]  148.13 99.06 270 bottom
PT8503  SE330U2VDM-4-GP  [CT7343H83]  148.13 94.24 270 bottom
PU4301  AON7403-GP-U  [PPAK-8P-3232H36]  32.07 84.97 180 top
PU4302  AON7403-GP-U  [PPAK-8P-3232H36]  28.87 85.12 270 top
PU4401  ISL9538HRTZ-GP-U  [QFN32J4-G2D85H34]  160.29 10.85 180 bottom
PU4403  AON7380-GP  [PPAK-8P-3232H36]  146.45 6.84 270 top
PU4404  AON7380-GP  [PPAK-8P-3232H36]  145.74 11.28 90 top
PU4405  AON7380-GP  [PPAK-8P-3232H36]  137.46 12.6 90 top
PU4406  AON7380-GP  [PPAK-8P-3232H36]  138.73 8.79 270 top
PU4412  AON7401-GP  [PPAK-8P-3232H36]  125.88 6.86 90 top
PU4413  AON7401-GP  [PPAK-8P-3232H36]  131.85 9.58 180 top
PU4501  SY8286BRAC-GP  [QFN20Z3-G1D1H36]  195.9 47.15 180 top
PU4502  SY8288CRAC-GP  [QFN20Z3-G1D1H36]  52.98 5.69 180 bottom
PU4601  ISL95859CHRTZ-T-1-GP  [QFN40J5-G3D6-DIFF-H34]  39.9 66.36 270 bottom
PU4701  AOZ5038QI-05-GP  [QFN31G5-G4P-9H34]  53.51 62.5 90 top
PU4801  AOZ5038QI-05-GP  [QFN31G5-G4P-9H34]  52.83 72.49 90 top
PU4802  AOZ5038QI-05-GP  [QFN31G5-G4P-9H34]  54.15 82.88 90 top
PU5001  ISL95808HRZ-T-1-GP  [DFN8G2-G1710-U1H40]  90.05 104.88 270 bottom
PU5002  AON7408-GP  [PPAK-8P-3232H36]  92.84 99.05 270 bottom
PU5003  AON7408-GP  [PPAK-8P-3232H36]  94.2 102.8 90 bottom
PU5101  G5388K11U-GP  [QFN32J4-G3PH32]  52.57 12.88 90 bottom
PU5102  APL5934KAI-TRG-GP-U  [SOIC8-G3530H63]  67.61 14.3 90 bottom
PU5201  AOZ2262QI-10-GP-U  [QFN22G4-G2PH42]  150.2 69.24 180 bottom
PU5301  APL5934KAI-TRG-GP-U  [SOIC8-G3530H63]  89.33 14.2 90 bottom
PU8510  FDMS3600-02-RJK0215-COLAY-GP  [PPAK-8P-G5324H44-COLAY]  131.11 103.13 180 top
PU8512  FDMS3600-02-RJK0215-COLAY-GP  [PPAK-8P-G5324H44-COLAY]  131.11 103.13 0 bottom
PU8514  RT8812AGQW-GP  [QFN20-G1D75H32]  119.76 100.13 0 top
PU8515  FDMS3600-02-RJK0215-COLAY-GP  [PPAK-8P-G5324H44-COLAY]  131.13 95.76 0 top
PU8516  FDMS3600-02-RJK0215-COLAY-GP  [PPAK-8P-G5324H44-COLAY]  131.13 95.76 180 bottom
PU8602  SY8288RAC-GP  [QFN20Z3-G1H36]  181.96 53.93 0 bottom
PU8603  RT5797ALGQW-GP  [DFN8-G125065H32]  146.68 85.91 270 bottom
Q401  2N7002KDW-1-GP  [SOT-363H44]  100.32 95.2 270 top
Q501  2N7002K-2-GP  [SOT23DGS2D4H44]  148.08 39.65 270 top
Q502  PJA138KA-GP  [SOT23DGS2D4H44]  144.77 39.17 0 top
Q1701  2N7002KDW-1-GP  [SOT-363H44]  116.45 44.07 90 top
Q1702  2N7002KDW-1-GP  [SOT-363H44]  119.37 44.33 270 top
Q1801  2N7002KDW-1-GP  [SOT-363H44]  146.45 75.39 270 bottom
Q1802  2N7002K-2-GP  [SOT23DGS2D4H44]  144.98 48.52 0 top
Q2001  2N7002KDW-1-GP  [SOT-363H44]  129.86 47.78 270 top
Q2408  2N7002K-2-GP  [SOT23DGS2D4H44]  24.28 42.5 270 bottom
Q2412  2N7002KDW-1-GP  [SOT-363H44]  55.37 35.38 180 top
Q2414  2N7002K-2-GP  [SOT23DGS2D4H44]  28.44 39.25 0 top
Q2417  2N7002KDW-1-GP  [SOT-363H44]  26.51 49.33 0 bottom
Q2501  2N7002K-2-GP  [SOT23DGS2D4H44]  209.75 9.65 0 top
Q2507  SM2421PSANC-TRG-GP  [SOT23DGS2D4H48]  191.4 26.27 90 bottom
Q2510  2N7002K-2-GP  [SOT23DGS2D4H44]  199.92 24.51 90 bottom
Q2601  2N7002KDW-1-GP  [SOT-363H44]  58.67 41.4 180 top
Q2602  2N7002K-2-GP  [SOT23DGS2D4H44]  23.41 41.23 270 top
Q2603  MMBT3904-5-GP-U  [SOT23CBE2D4H46-U]  60.54 55.96 0 bottom
Q2704  SM2421PSANC-TRG-GP  [SOT23DGS2D4H48]  57.12 56.06 180 bottom
Q2705  2N7002K-2-GP  [SOT23DGS2D4H44]  57.22 51.56 180 top
Q4001  2N7002KDW-1-GP  [SOT-363H44]  214.66 44.05 270 top
Q4301  PJA138KA-GP  [SOT23DGS2D4H44]  16.55 96.9 180 bottom
Q4302  MMBT3904-3-GP  [SOT23CBE2D4H44]  30.42 97.79 0 top
Q4304  LMUN5212T1G-GP  [SOT323CBE2D2H40]  27.02 81.23 180 bottom
Q4305  LTA024EUB-FS8-GP  [SC70-2D2-312H44]  27.58 85.32 0 bottom
Q4348  PJA3415-GP  [SOT23DGS2D4H44]  34.94 78.74 90 bottom
Q4349  2N7002KDW-1-GP  [SOT-363H44]  31.62 79.07 90 bottom
Q5701  2N7002K-2-GP  [SOT23DGS2D4H44]  18.28 68 90 bottom
Q5702  2N7002KDW-1-GP  [SOT-363H44]  18.21 64.72 180 bottom
Q5703  LMBT3904LT1G-GP  [SOT23CBE2D4H44]  21.05 69.85 0 bottom
Q6101  PJA3415-GP  [SOT23DGS2D4H44]  221.05 58.78 0 bottom
Q6102  2N7002K-2-GP  [SOT23DGS2D4H44]  27.65 56.87 90 top
Q6401  PJA138KA-GP  [SOT23DGS2D4H44]  25.47 98.17 90 top
Q6402  PJT138KA-GP  [SOT-363H44]  20.95 98.86 90 top
Q6403  RN2418-GP  [SOT23CBE2D6H62]  16.2 90.17 0 bottom
Q6404  RN2418-GP  [SOT23CBE2D6H62]  16.12 93.55 270 bottom
Q6501  PJA3402-R1-00001-GP  [SOT23DGS2D4H44]  104.85 11.84 0 bottom
Q6502  RN2418-GP  [SOT23CBE2D6H62]  95.29 15.62 270 bottom
Q6503  2N7002KDW-1-GP  [SOT-363H44]  181.12 17.55 0 bottom
Q6504  SM2421PSANC-TRG-GP  [SOT23DGS2D4H48]  169.77 16.28 90 bottom
Q6505  2N7002K-2-GP  [SOT23DGS2D4H44]  168.98 7.7 180 bottom
Q7001  2N7002KDW-1-GP  [SOT-363H44]  216.2 61.7 270 top
Q7404  2N7002KDW-1-GP  [SOT-363H44]  27.6 80.85 0 top
Q7405  2N7002KDW-1-GP  [SOT-363H44]  24.12 82.4 270 bottom
Q7406  PJT138KA-GP  [SOT-363H44]  30.52 81.82 90 top
Q7407  PJT138KA-GP  [SOT-363H44]  30.02 83.09 0 bottom
Q7601  2N7002K-2-GP  [SOT23DGS2D4H44]  172.66 94.31 0 bottom
Q7901  2N7002KDW-1-GP  [SOT-363H44]  177.97 58.63 0 bottom
Q7904  PJA138KA-GP  [SOT23DGS2D4H44]  166.16 77.35 0 bottom
Q7906  2N7002K-2-GP  [SOT23DGS2D4H44]  199.67 74.88 90 bottom
Q7907  PJT138KA-GP  [SOT-363H44]  181.07 63.1 0 bottom
Q8101  2N7002K-2-GP  [SOT23DGS2D4H44]  205.86 103.08 270 top
Q8504  2N7002K-2-GP  [SOT23DGS2D4H44]  105.23 104.37 90 top
Q8509  PJT138KA-GP  [SOT-363H44]  108.12 104.57 180 top
Q8601  PJA138KA-GP  [SOT23DGS2D4H44]  147.85 89.99 90 bottom
Q8602  2N7002K-2-GP  [SOT23DGS2D4H44]  167.3 100.38 180 bottom
Q8603  2N7002K-2-GP  [SOT23DGS2D4H44]  165.88 102.87 0 bottom
Q8604  2N7002K-2-GP  [SOT23DGS2D4H44]  155.33 75.65 180 bottom
Q8605  2N7002K-2-GP  [SOT23DGS2D4H44]  101.16 106.13 270 top
Q8606  PJT138KA-GP  [SOT-363H44]  169.69 95.46 180 bottom
Q8607  PJT138KA-GP  [SOT-363H44]  156.81 99.16 180 bottom
Q8608  2N7002KDW-1-GP  [SOT-363H44]  163.18 100.49 270 bottom
Q8609  PJT138KA-GP  [SOT-363H44]  174.68 63.86 180 bottom
Q8612  PJA3415-GP  [SOT23DGS2D4H44]  37.46 78.95 270 top
R301  1KR2J-1-GP  [R402H16]  91.23 92.28 270 bottom
R302  499R2F-2-GP  [R402H16]  91.98 91.04 180 bottom
R303  100KR2J-1-GP  [R402H16]  136.39 46.76 90 top
R304  49D9R2F-GP  [R402H16]  113.33 73.31 270 top
R305  49D9R2F-GP  [R402H16]  124.07 69.09 180 top
R308  1KR2J-1-GP  [R402H16]  110.53 96.14 0 top
R309  51R2J-2-GP  [R402H16]  91.22 90.91 0 bottom
R310  51R2J-2-GP  [R402H16]  85.7 90.71 0 bottom
R311  51R2J-2-GP  [R402H16]  83.19 90.71 0 bottom
R312  51R2J-2-GP  [R402H16]  83.95 90.71 0 bottom
R313  51R2J-2-GP  [R402H16]  84.94 90.71 0 bottom
R314  51R2J-2-GP  [R402H16]  90.45 90.91 0 bottom
R315  1KR2J-1-GP  [R402H16]  89.53 90.58 0 bottom
R316  51R2J-2-GP  [R402H16]  95.78 79.91 0 top
R317  51R2J-2-GP  [R402H16]  92.53 80.5 0 top
R318  51R2J-2-GP  [R402H16]  93.49 79.17 270 top
R319  0R0402-PAD-2-GP  [0R0402-PAD-1]  137.23 44.73 270 top
R401  24D9R2F-L-GP  [R402H16]  102.11 69.24 270 top
R402  10KR2J-3-GP  [R402H16]  129.89 79.12 0 top
R403  100KR2J-1-GP  [R402H16]  103.73 95.63 270 top
R404  0R2J-L-GP  [R402H15]  102.38 95.1 0 top
R405  10KR2J-3-GP  [R402H16]  103.73 94.77 270 top
R406  10KR2J-3-GP  [R402H16]  100.27 93.55 270 top
R501  121R2F-GP  [R402H16]  108.83 50.6 0 top
R502  80D6R2F-L-GP  [R402H16]  108.07 50.6 0 top
R503  100R2F-L1-GP-U  [R402H14]  109.6 50.6 0 top
R504  0R0402-PAD-2-GP  [0R0402-PAD-1]  148.08 43.34 0 top
R505  470R2F-GP  [R402H16]  147.29 43.34 180 top
R506  220KR2F-GP  [R402H16]  149.9 41.15 270 top
R507  10KR2J-3-GP  [R402H16]  142.6 39.26 0 top
R601  49D9R2F-GP  [R402H16]  96.54 79.91 0 top
R709  0R0402-PAD-2-GP  [0R0402-PAD-1]  95.64 90.22 0 bottom
R719  100R2F-L1-GP-U  [R402H14]  103.8 79.3 180 top
R720  100R2F-L1-GP-U  [R402H14]  103.03 79.3 0 top
R723  54D9R2F-L1-GP  [R402H16]  93.6 90.99 90 bottom
R726  100R2F-L1-GP-U  [R402H14]  94.84 91.1 180 bottom
R727  56R2J-4-GP  [R402H16]  97.99 91.49 90 bottom
R728  220R2J-L2-GP  [R402H16]  96.74 91.06 180 bottom
R732  0R0402-PAD-2-GP  [0R0402-PAD-1]  93.48 90.22 90 bottom
R807  100R2F-L1-GP-U  [R402H14]  86.14 80.52 180 top
R808  100R2F-L1-GP-U  [R402H14]  85.32 80.52 0 top
R809  100R2F-L1-GP-U  [R402H14]  111.7 79.07 270 top
R810  100R2F-L1-GP-U  [R402H14]  112.92 79.35 180 top
R812  D0002R5J-GP-U  [R805H20]  97.61 76.99 270 top
R813  D0002R5J-GP-U  [R805H20]  98.32 79.28 270 top
R814  D0002R5J-GP-U  [R805H20]  101.75 76.51 180 top
R815  D0002R5J-GP-U  [R805H20]  101.11 79.35 270 top
R816  D0002R5J-GP-U  [R805H20]  99.99 76.51 180 top
R1103  0R0603-PAD-2-GP-U  [0R0603-PAD-1-U]  146.55 88.27 270 top
R1104  0R0603-PAD-2-GP-U  [0R0603-PAD-1-U]  145.49 70.23 270 top
R1204  10KR2F-L1-GP  [R402H15]  97.07 20.17 90 top
R1205  0R0603-PAD-2-GP-U  [0R0603-PAD-1-U]  95.04 20.27 90 top
R1206  2R2F-GP  [R402H16]  71.09 19.99 270 top
R1208  10KR2F-L1-GP  [R402H15]  98.77 20.32 270 top
R1209  24D9R2F-L-GP  [R402H16]  70.91 18.37 270 top
R1210  0R0603-PAD-2-GP-U  [0R0603-PAD-1-U]  101.04 20.07 270 top
R1211  10KR2F-L1-GP  [R402H15]  75.91 19.15 90 top
R1212  0R0603-PAD-2-GP-U  [0R0603-PAD-1-U]  75.81 20.2 270 top
R1215  240R2F-1-GP  [R402H16]  64.69 20.02 90 top
R1302  10KR2F-L1-GP  [R402H15]  178.35 19 270 top
R1303  0R0402-PAD-2-GP  [0R0402-PAD-1]  175.81 18.75 90 top
R1305  2R2F-GP  [R402H16]  150.29 17.83 270 top
R1306  10KR2F-L1-GP  [R402H15]  178.35 21.41 270 top
R1307  0R2J-L-GP  [R402H15]  178.35 20.65 270 top
R1309  24D9R2F-L-GP  [R402H16]  148.41 19.05 180 top
R1310  10KR2F-L1-GP  [R402H15]  153.97 18.93 180 top
R1311  0R0402-PAD-2-GP  [0R0402-PAD-1]  154.43 20.14 270 top
R1312  240R2F-1-GP  [R402H16]  142.67 20.53 270 top
R1501  20KR2J-L2-GP  [R402H16]  126.56 57 0 bottom
R1502  1KR2J-1-GP  [R402H16]  127.55 64.82 270 top
R1503  1KR2J-1-GP  [R402H16]  130.32 55.22 180 bottom
R1504  4K7R2J-L-GP  [R402H15]  147.16 79 270 bottom
R1505  20K5R2F-GP  [R402H16]  148.84 79 270 bottom
R1506  100KR2F-L2-GP  [R402H16]  136.75 49.02 180 top
R1507  4K7R2J-L-GP  [R402H15]  133.34 46.92 0 top
R1508  100KR2F-L2-GP  [R402H16]  132.04 52.14 0 top
R1509  4K7R2J-L-GP  [R402H15]  132.83 52.14 0 top
R1510  100KR2F-L2-GP  [R402H16]  131.23 52.14 0 top
R1511  4K7R2J-L-GP  [R402H15]  130.42 52.15 0 top
R1512  4K7R2J-L-GP  [R402H15]  112.31 48.47 180 top
R1513  4K7R2J-L-GP  [R402H15]  138.91 67.8 270 bottom
R1514  4K7R2J-L-GP  [R402H15]  140.63 67.8 270 bottom
R1515  20KR2J-L2-GP  [R402H16]  145.26 62.28 270 top
R1516  4K7R2J-L-GP  [R402H15]  145.26 61.52 90 top
R1517  1KR2J-1-GP  [R402H16]  90.55 87.58 270 bottom
R1518  1KR2J-1-GP  [R402H16]  87.99 89.94 0 bottom
R1519  10KR2J-3-GP  [R402H16]  132.76 71.86 0 bottom
R1520  4K7R2J-L-GP  [R402H15]  144.8 45.21 90 top
R1521  4K7R2J-L-GP  [R402H15]  146.3 45.82 180 top
R1522  4K7R2J-L-GP  [R402H15]  142.51 72.39 90 bottom
R1523  20K5R2F-GP  [R402H16]  139.9 73.15 270 bottom
R1524  20K5R2F-GP  [R402H16]  145.05 46.46 180 top
R1525  100KR2F-L2-GP  [R402H16]  143.53 45.75 180 top
R1527  1KR2J-1-GP  [R402H16]  130.35 66.2 90 top
R1551  4K7R2J-L-GP  [R402H15]  143.73 72.82 180 bottom
R1552  20K5R2F-GP  [R402H16]  145.28 70.82 270 bottom
R1553  20K5R2F-GP  [R402H16]  127.38 56.16 0 bottom
R1554  20KR2J-L2-GP  [R402H16]  134.54 70.44 90 bottom
R1555  20KR2J-L2-GP  [R402H16]  134.41 46.87 0 top
R1603  113R2F-GP  [R402H16]  128.22 80.8 0 top
R1604  100R2F-L1-GP-U  [R402H14]  125.77 80.06 180 top
R1606  10KR2J-3-GP  [R402H16]  141.73 76.74 90 bottom
R1608  10KR2J-3-GP  [R402H16]  141.73 75.97 90 bottom
R1701  10KR2J-3-GP  [R402H16]  140.51 75.26 0 bottom
R1702  1KR2J-1-GP  [R402H16]  117.32 45.72 270 top
R1704  0R0402-PAD-2-GP  [0R0402-PAD-1]  118.1 52.25 180 top
R1706  0R0402-PAD-2-GP  [0R0402-PAD-1]  117.34 52.33 180 top
R1707  10KR2J-3-GP  [R402H16]  119.42 66.3 90 top
R1708  0R2J-2-GP  [R402H16]  121.15 52.83 0 top
R1713  0R0402-PAD-2-GP  [0R0402-PAD-1]  129.79 44.76 270 top
R1714  10KR2J-3-GP  [R402H16]  105.91 88.42 270 bottom
R1715  100KR2J-1-GP  [R402H16]  131.69 44.17 90 top
R1716  100KR2F-L1-GP  [R402H16]  113.51 93.55 0 top
R1717  10KR2J-3-GP  [R402H16]  138.53 73 180 bottom
R1718  100KR2F-L1-GP  [R402H16]  110.74 92.89 270 top
R1719  47KR2F-GP  [R402H16]  112.74 93.55 180 top
R1721  10KR2J-3-GP  [R402H16]  121.1 49.86 180 top
R1722  10KR2J-3-GP  [R402H16]  118.69 49.86 180 top
R1723  10KR2J-3-GP  [R402H16]  119.65 52.78 0 top
R1724  100KR2J-1-GP  [R402H16]  210.64 32.11 270 top
R1726  10KR2J-3-GP  [R402H16]  112.39 43.18 0 top
R1727  100KR2J-1-GP  [R402H16]  113.2 42.32 0 top
R1728  0R0402-PAD-2-GP  [0R0402-PAD-1]  113.58 41 90 top
R1730  330KR2J-L1-GP  [R402H16]  114.75 47.75 180 top
R1731  100KR2F-L2-GP  [R402H16]  145.26 64.82 270 top
R1737  100KR2J-1-GP  [R402H16]  121.23 43.34 180 top
R1738  10KR2J-3-GP  [R402H16]  121.94 52.83 180 top
R1803  60D4R2F-GP  [R402H16]  129.38 88.39 270 bottom
R1805  33R2F-3-GP  [R402H16]  123.44 49.86 0 top
R1814  0R0402-PAD-2-GP  [0R0402-PAD-1]  157.6 49.28 0 top
R1815  10MR2J-L-GP  [R402H16]  112.19 52.68 90 top
R1816  10KR2J-3-GP  [R402H16]  141.29 47.4 0 top
R1818  8K2R2F-1-GP  [R402H16]  136.01 51.31 0 top
R1819  0R0402-PAD-2-GP  [0R0402-PAD-1]  157.12 46.26 270 top
R1820  10KR2J-3-GP  [R402H16]  136.8 51.31 180 top
R1821  10KR2J-3-GP  [R402H16]  133.85 38.94 270 top
R1822  10KR2J-3-GP  [R402H16]  166.41 64.57 270 top
R1823  0R0402-PAD-2-GP  [0R0402-PAD-1]  133.29 48.42 270 top
R1824  0R0402-PAD-2-GP  [0R0402-PAD-1]  132.46 53.42 270 top
R1837  150KR2J-GP  [R402H16]  135.17 46.87 180 top
R1839  0R0402-PAD-2-GP  [0R0402-PAD-1]  136.32 78.62 270 bottom
R1840  0R0402-PAD-2-GP  [0R0402-PAD-1]  136.32 79.38 270 bottom
R1841  1MR2J-1-GP  [R402H16]  138.4 79.1 0 bottom
R1842  0R0402-PAD-2-GP  [0R0402-PAD-1]  157.4 85.4 90 top
R1843  0R0402-PAD-2-GP  [0R0402-PAD-1]  145.87 79.4 0 bottom
R1845  0R0402-PAD-2-GP  [0R0402-PAD-1]  130.3 53.44 270 top
R1901  200R2F-L-GP  [R402H16]  133.85 52.96 0 top
R1908  0R0402-PAD-2-GP  [0R0402-PAD-1]  115.03 52.99 180 top
R1909  1KR2J-1-GP  [R402H16]  110.66 48.47 180 top
R1910  10KR2J-3-GP  [R402H16]  131.87 49.96 90 top
R1911  10KR2J-3-GP  [R402H16]  132.56 46.92 0 top
R1912  10KR2J-3-GP  [R402H16]  122.68 49.86 0 top
R1913  10KR2J-3-GP  [R402H16]  121.89 49.86 180 top
R1920  0R2J-L-GP  [R402H15]  113.71 48.47 180 top
R1921  33R2J-2-GP  [R402H16]  111.53 48.47 180 top
R1922  33R2J-2-GP  [R402H16]  210.99 51.46 90 top
R1923  33R2J-2-GP  [R402H16]  144.82 63.55 180 top
R2001  10KR2F-2-GP  [R402H16]  130.83 50.73 270 top
R2002  10KR2J-3-GP  [R402H16]  127.98 47.58 0 top
R2003  0R2J-L-GP  [R402H15]  129.08 52.99 180 top
R2004  0R2J-L-GP  [R402H15]  128.7 66.88 180 top
R2005  10KR2J-3-GP  [R402H16]  129.76 72.04 180 top
R2006  75R2J-1-GP  [R402H16]  145.05 60.35 270 top
R2007  75R2J-1-GP  [R402H16]  205.43 50.29 0 top
R2008  10KR2J-3-GP  [R402H16]  129.56 73.61 270 top
R2009  10KR2J-3-GP  [R402H16]  128.37 78.84 0 top
R2010  10KR2J-3-GP  [R402H16]  129.13 79.12 180 top
R2011  10KR2J-3-GP  [R402H16]  136.32 68.4 90 bottom
R2020  0R0402-PAD-2-GP  [0R0402-PAD-1]  153.23 76.69 0 bottom
R2021  0R0402-PAD-2-GP  [0R0402-PAD-1]  152.47 76.69 0 bottom
R2025  0R0402-PAD-2-GP  [0R0402-PAD-1]  163.49 51.64 180 top
R2026  0R0402-PAD-2-GP  [0R0402-PAD-1]  122.83 52.94 0 top
R2027  0R0402-PAD-2-GP  [0R0402-PAD-1]  139.44 46.97 90 top
R2028  0R2J-L-GP  [R402H15]  119.3 46.84 0 top
R2029  20KR2J-L2-GP  [R402H16]  127.54 73.58 270 top
R2030  20KR2J-L2-GP  [R402H16]  128 71.21 180 top
R2037  10KR2J-3-GP  [R402H16]  142.34 69.34 270 bottom
R2038  10KR2J-3-GP  [R402H16]  142.32 68.54 90 bottom
R2041  10KR2J-3-GP  [R402H16]  136.37 74.55 0 bottom
R2043  10KR2J-3-GP  [R402H16]  127.81 50.45 0 top
R2044  10KR2J-3-GP  [R402H16]  141.83 73.38 90 bottom
R2045  10KR2J-3-GP  [R402H16]  137.15 74.55 0 bottom
R2046  10KR2J-3-GP  [R402H16]  136.32 67.64 90 bottom
R2048  51KR2J-1-GP  [R402H16]  129.89 77.45 0 top
R2049  51KR2J-1-GP  [R402H16]  129.13 77.45 0 top
R2050  10KR2J-3-GP  [R402H16]  128.98 45.9 90 top
R2051  10KR2J-3-GP  [R402H16]  120.82 46.84 0 top
R2052  10KR2J-3-GP  [R402H16]  120.06 46.84 180 top
R2053  10KR2J-3-GP  [R402H16]  137.56 52.35 180 top
R2101  150R2F-1-GP  [R402H16]  130.35 65.43 90 top
R2107  10KR2J-3-GP  [R402H16]  135.22 51.31 180 top
R2108  200R2F-L-GP  [R402H16]  128.34 75.36 90 top
R2109  10KR2J-3-GP  [R402H16]  133.93 74.3 90 bottom
R2111  10KR2J-3-GP  [R402H16]  140.63 69.37 90 bottom
R2112  10KR2J-3-GP  [R402H16]  140.63 68.61 270 bottom
R2113  10KR2J-3-GP  [R402H16]  131.87 55.22 0 bottom
R2114  10KR2J-3-GP  [R402H16]  131.11 55.22 180 bottom
R2115  10KR2J-3-GP  [R402H16]  140.61 70.61 0 bottom
R2116  10KR2J-3-GP  [R402H16]  141.85 71.2 270 bottom
R2117  10KR2J-3-GP  [R402H16]  138.33 70.06 90 bottom
R2118  10KR2J-3-GP  [R402H16]  137.08 70.51 0 bottom
R2119  10KR2J-3-GP  [R402H16]  134.72 75.06 90 bottom
R2120  10KR2J-3-GP  [R402H16]  134.72 75.82 270 bottom
R2202  0R0603-PAD-2-GP-U  [0R0603-PAD-1-U]  123.87 93.37 0 top
R2203  0R0603-PAD-2-GP-U  [0R0603-PAD-1-U]  121.07 76.73 270 top
R2204  0R0603-PAD-2-GP-U  [0R0603-PAD-1-U]  145.28 51.36 270 top
R2205  0R0603-PAD-2-GP-U  [0R0603-PAD-1-U]  117.67 93.4 0 top
R2401  0R0402-PAD-2-GP  [0R0402-PAD-1]  23.59 38.33 270 top
R2402  0R0402-PAD-2-GP  [0R0402-PAD-1]  30.02 34.37 90 top
R2403  150KR2F-L-GP  [R402H16]  29.08 52.83 90 bottom
R2404  115KR2F-GP  [R402H16]  29.08 52.07 270 bottom
R2405  0R2J-L-GP  [R402H15]  22.14 38.64 0 top
R2406  0R2J-2-GP  [R402H16]  50.16 37.39 270 top
R2407  0R0402-PAD-2-GP  [0R0402-PAD-1]  122.51 55.96 0 bottom
R2414  10KR2F-2-GP  [R402H16]  28.77 41.2 270 top
R2415  10KR2J-3-GP  [R402H16]  51.1 50.04 270 top
R2416  0R0402-PAD-2-GP  [0R0402-PAD-1]  24.81 46.05 90 top
R2417  100KR2J-1-GP  [R402H16]  25.19 44.55 180 top
R2418  0R2J-L-GP  [R402H15]  24.4 44.55 180 top
R2419  0R0402-PAD-2-GP  [0R0402-PAD-1]  39.72 34.52 90 top
R2420  100KR2J-1-GP  [R402H16]  51.63 39.93 180 top
R2421  0R0402-PAD-2-GP  [0R0402-PAD-1]  42.72 54.92 0 top
R2422  0R0402-PAD-2-GP  [0R0402-PAD-1]  49.91 41.13 270 top
R2423  330R2J-3-GP  [R402H16]  26.08 26.27 180 top
R2424  20KR2F-L-GP  [R402H16]  54.35 47.93 90 top
R2426  10KR2J-3-GP  [R402H16]  56.33 46.51 270 top
R2427  0R2J-L-GP  [R402H15]  30.4 55.68 0 top
R2428  0R2J-L-GP  [R402H15]  45.51 33.94 90 top
R2429  10KR2J-3-GP  [R402H16]  44.93 53.98 180 top
R2430  0R2J-L-GP  [R402H15]  221 22.91 90 top
R2431  0R2J-L-GP  [R402H15]  40.51 56.06 90 top
R2432  1KR2J-1-GP  [R402H16]  51.38 31.19 90 top
R2434  100KR2J-1-GP  [R402H16]  52.62 41.99 270 top
R2435  0R2J-2-GP  [R402H16]  53.38 37.67 270 top
R2436  100KR2J-1-GP  [R402H16]  24.45 36.81 90 top
R2437  43R2J-GP  [R402H16]  27.98 35.47 270 top
R2438  0R0402-PAD-2-GP  [0R0402-PAD-1]  53.36 40.95 90 top
R2439  0R0402-PAD-2-GP  [0R0402-PAD-1]  55.04 40.57 90 top
R2440  100KR2J-1-GP  [R402H16]  214.04 26.7 90 top
R2441  100KR2F-L1-GP  [R402H16]  36.47 33.4 270 top
R2442  64K9R2F-1-GP  [R402H16]  36.47 30.97 180 top
R2443  49K9R2F-L-GP  [R402H16]  37.23 31.47 180 top
R2444  100KR2F-L1-GP  [R402H16]  38.5 30.97 90 top
R2445  0R0402-PAD-2-GP  [0R0402-PAD-1]  39.06 33.23 180 top
R2446  0R0603-PAD-2-GP-U  [0R0603-PAD-1-U]  37.28 29.39 270 top
